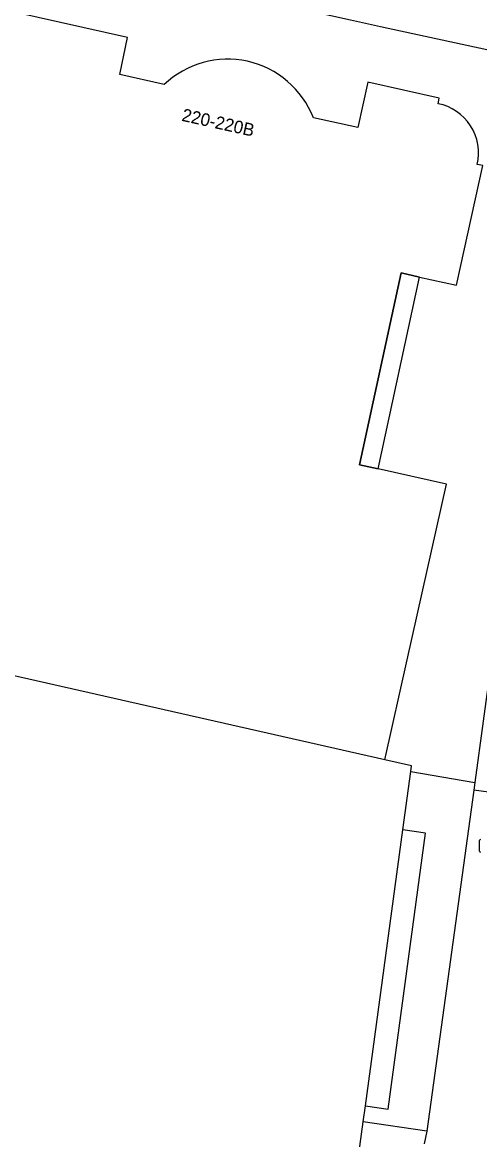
# Model space of a CAD drawing. Extents: x 162172 to 163187, y 382874 to 383684.
# Drawn here: x 163062.4 to 163098.4, y 382962.2 to 383050.2 of the extents above; entities that cross this region are included whole.
import ezdxf

# ---------------------------------------------------------------- set-up
doc = ezdxf.new("R2010")
doc.units = 0
for name, color, linetype in [('IMGEO_Brandkraan', 7, 'Continuous'), ('IMGEO_Pand', 7, 'Continuous'), ('IMGEO_Pand_nummerreeks', 7, 'Continuous'), ('IMGEO_Pand_overbouw', 7, 'Continuous'), ('IMGEO_Voetpad_gesloten', 7, 'Continuous'), ('IMGEO_Voetpad_open', 7, 'Continuous')]:
    doc.layers.add(name, color=color, linetype=linetype)

msp = doc.modelspace()

# ---------------------------------------------------------------- linework, layer by layer
at = {"layer": 'IMGEO_Brandkraan'}
msp.add_line((163098.377, 382984.91), (163098.377, 382985.762), dxfattribs=at)
msp.add_lwpolyline([(163098.377, 382984.91), (163098.377, 382985.762)], dxfattribs=at)
for centre, start, end in [((163098.454, 382985.76), 91.55205, 178.44795), ((163098.454, 382985.76), 91.55205, 178.44795), ((163098.454, 382984.912), 181.55205, 268.44795), ((163098.454, 382984.912), 181.55205, 268.44795)]:
    msp.add_arc(centre, 0.0765, start, end, dxfattribs=at)
at = {"layer": 'IMGEO_Pand'}
for points in [[(163073.528, 383045.327), (163070.025, 383046.107), (163070.646, 383049.031), (163061.84, 383050.987)], [(163095.102, 383043.807), (163095.194, 383044.255), (163089.58, 383045.511), (163088.795, 383041.942), (163085.284, 383042.69)], [(163090.912, 382992.113), (163092.68, 383000), (163095.779, 383013.826), (163090.381, 383015.036), (163088.911, 383015.365), (163092.186, 383030.473), (163093.637, 383030.155), (163096.551, 383029.516), (163098.631, 383038.933), (163098.172, 383039.026)], [(163090.912, 382992.113), (163056.116, 383000), (163050.852, 383001.172)], [(163092.948, 382991.201), (163093.008, 382991.643), (163090.912, 382992.113)], [(163092.325, 382986.594), (163092.948, 382991.201)], [(163089.383, 382964.848), (163092.325, 382986.594)], [(163089.213, 382963.592), (163089.383, 382964.848)], [(163078.547, 382918.193), (163082.937, 382917.209), (163089.213, 382963.592)]]:
    msp.add_lwpolyline(points, dxfattribs=at)
for centre, radius, start, end in [((163078.57, 383039.934), 7.383, 78.08289, 133.076), ((163078.462, 383040.015), 7.327, 21.41394, 77.12573), ((163094.378, 383039.966), 3.909, 346.08376, 79.32731)]:
    msp.add_arc(centre, radius, start, end, dxfattribs=at)
at = {"layer": 'IMGEO_Pand_overbouw'}
msp.add_lwpolyline([(163090.381, 383015.036), (163093.637, 383030.155), (163092.186, 383030.473), (163088.911, 383015.365)], close=True, dxfattribs=at)
at = {"layer": 'IMGEO_Voetpad_gesloten'}
for points in [[(163092.948, 382991.201), (163097.992, 382990.342)], [(163097.992, 382990.342), (163097.909, 382989.737)], [(163097.909, 382989.737), (163094.223, 382962.874)], [(163089.383, 382964.848), (163091.162, 382964.606), (163094.125, 382986.349), (163092.325, 382986.594)], [(163094.223, 382962.874), (163089.213, 382963.592)]]:
    msp.add_lwpolyline(points, dxfattribs=at)
at = {"layer": 'IMGEO_Voetpad_open'}
for points in [[(163083.554, 383051.437), (163088.206, 383050.416), (163090.563, 383049.905), (163100.899, 383047.662), (163102.739, 383047.263)], [(163105.322, 383043.799), (163102.12, 383020.545), (163099.312, 383000), (163097.992, 382990.342)], [(163101.209, 382989.271), (163097.909, 382989.737)], [(163094.223, 382962.874), (163094.005, 382961.869)]]:
    msp.add_lwpolyline(points, dxfattribs=at)

# ---------------------------------------------------------------- texts
at = {"layer": 'IMGEO_Pand_nummerreeks'}
msp.add_text('220-220B', height=1, rotation=347.44649, dxfattribs=at).set_placement((163074.852, 383042.471))

doc.saveas('drawing.dxf')
